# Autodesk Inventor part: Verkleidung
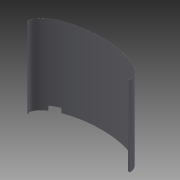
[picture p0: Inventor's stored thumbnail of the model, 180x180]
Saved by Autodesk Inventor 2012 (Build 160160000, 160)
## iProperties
Created: 2012-01
Part Number: Verkleidung
Material: Edelstahl
Document SubType Name: Blech
Designer: Stefan
Mass: 5945.9 g
Surface Area: 15293.1 cm^2
Volume: 735.879 cm^3
Density: 8.08 g/cm^3
Sheet Metal Rule: Standard
Sheet Metal Width: 901,896 mm
Sheet Metal Length: 700,000 mm
Sheet Metal Area: 631327,232 mm^2
Flat Pattern Width: 90.1896 cm
Flat Pattern Length: 70 cm
Flat Pattern Area: 6313.27 cm^2
Author: Stefan
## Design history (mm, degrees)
sketch "Skizze1" dims "d0" = 450, "d1" = 200, "d2" = 451, "d3" = 201
  geometry: L1 (-449.994, 1)-(-435, 1); L2 (-435, 1)-(-435, 0); L3 (-435, 0)-(-451, 0); L4 (435, 0)-(435, 1); L5 (435, 1)-(450, 1); L6 (435, 0)-(451, 0); 4 further points; 2 other entities
  constraints: 12 end point, 4 perpendicular, 2 coincident, 1 horizontal, 1 parallel, 1 point on line, 8 other
  dimensions: "d4" = 1 distance of L1.end L2.end; "d6" = 0 vertical distance of point (0, 0) L2.end; "d7" = 1 distance of L4.start L4.end; "d8" = 0 vertical distance of point (0, 0) L4.start; "d9" = 15 distance of L4.end L5.end; "d10" = 435 distance from line of point (0, 0) L4; "d11" = 435 distance from line of point (0, 0) L2
extrude "Extrusion1" new body sketch "Skizze1" stored distance "d12" = 700; taper "d13" = 0 deg
fillet "Rundung1" dims "d14" = 2
fillet "Rundung2" dims "d15" = 3
sketch "Skizze2"
  geometry: L1 (116, -310)-(144, -310) reference; L2 (150, -316)-(150, -344) reference; L3 (110, -344)-(110, -316) reference; L4 (116, -310)-(144, -310); L5 (150, -316)-(150, -355.272); L6 (150, -355.272)-(110, -355.272); L7 (110, -355.272)-(110, -316); A1 r 6 centre (116, -316) between (116, -310) and (110, -316); A2 r 6 centre (144, -316) between (150, -316) and (144, -310); 1 further point
  constraints: 8 end point, 4 point on circle, 3 perpendicular, 2 centre point, 1 collinear, 2 other
feature "Ausklinkung1" sketch "Skizze2" dims "d16" = 1 (= Stärke), "d17" = 0
node "Volumenkörper1"
node "Referenz1"
node "Referenz2"
node "Referenz3"
node "Referenz4"
node "Referenz5"
feature "Definition1"
other parameters: "Stärke" = 1 (derived), "KFaktor" = 4.4, "Biegeradius" = 1 (= Stärke), "BreiteBiegungsfreistellung" = 1 (= Stärke), "TiefeBiegungsfreistellung" = 0.5 (= 0.5 x Stärke), "GrößeEckenfreistellung" = 4 (= 4 x Stärke), "AbstandVerbindung" = 0.01, "MinimalRest" = 2 (= 2 x Stärke), "Übergangsradius" = 1 (= Biegeradius), "JacobiRadiusGröße" = 1 (= Biegeradius), "Abstandsgröße" = 1 (= Stärke), "Abstandsgröße" = 1, "Biegeradius" = 1, "BreiteBiegungsfreistellung" = 1, "GrößeEckenfreistellung" = 4, "JacobiRadiusGröße" = 1, "MinimalRest" = 2, "Stärke" = 1, "TiefeBiegungsfreistellung" = 0.5, "Übergangsradius" = 1
